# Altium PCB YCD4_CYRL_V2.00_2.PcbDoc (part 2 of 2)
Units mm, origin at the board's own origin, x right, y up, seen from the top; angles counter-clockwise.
Board outline 53 x 53 mm, 6 copper layers (Top Layer, Mid-Layer 1, Mid-Layer 3, Mid-Layer 4, Mid-Layer 5, Bottom Layer), stack 0.996 mm thick; 207 components, 114 nets, 645 pads, 437 vias.
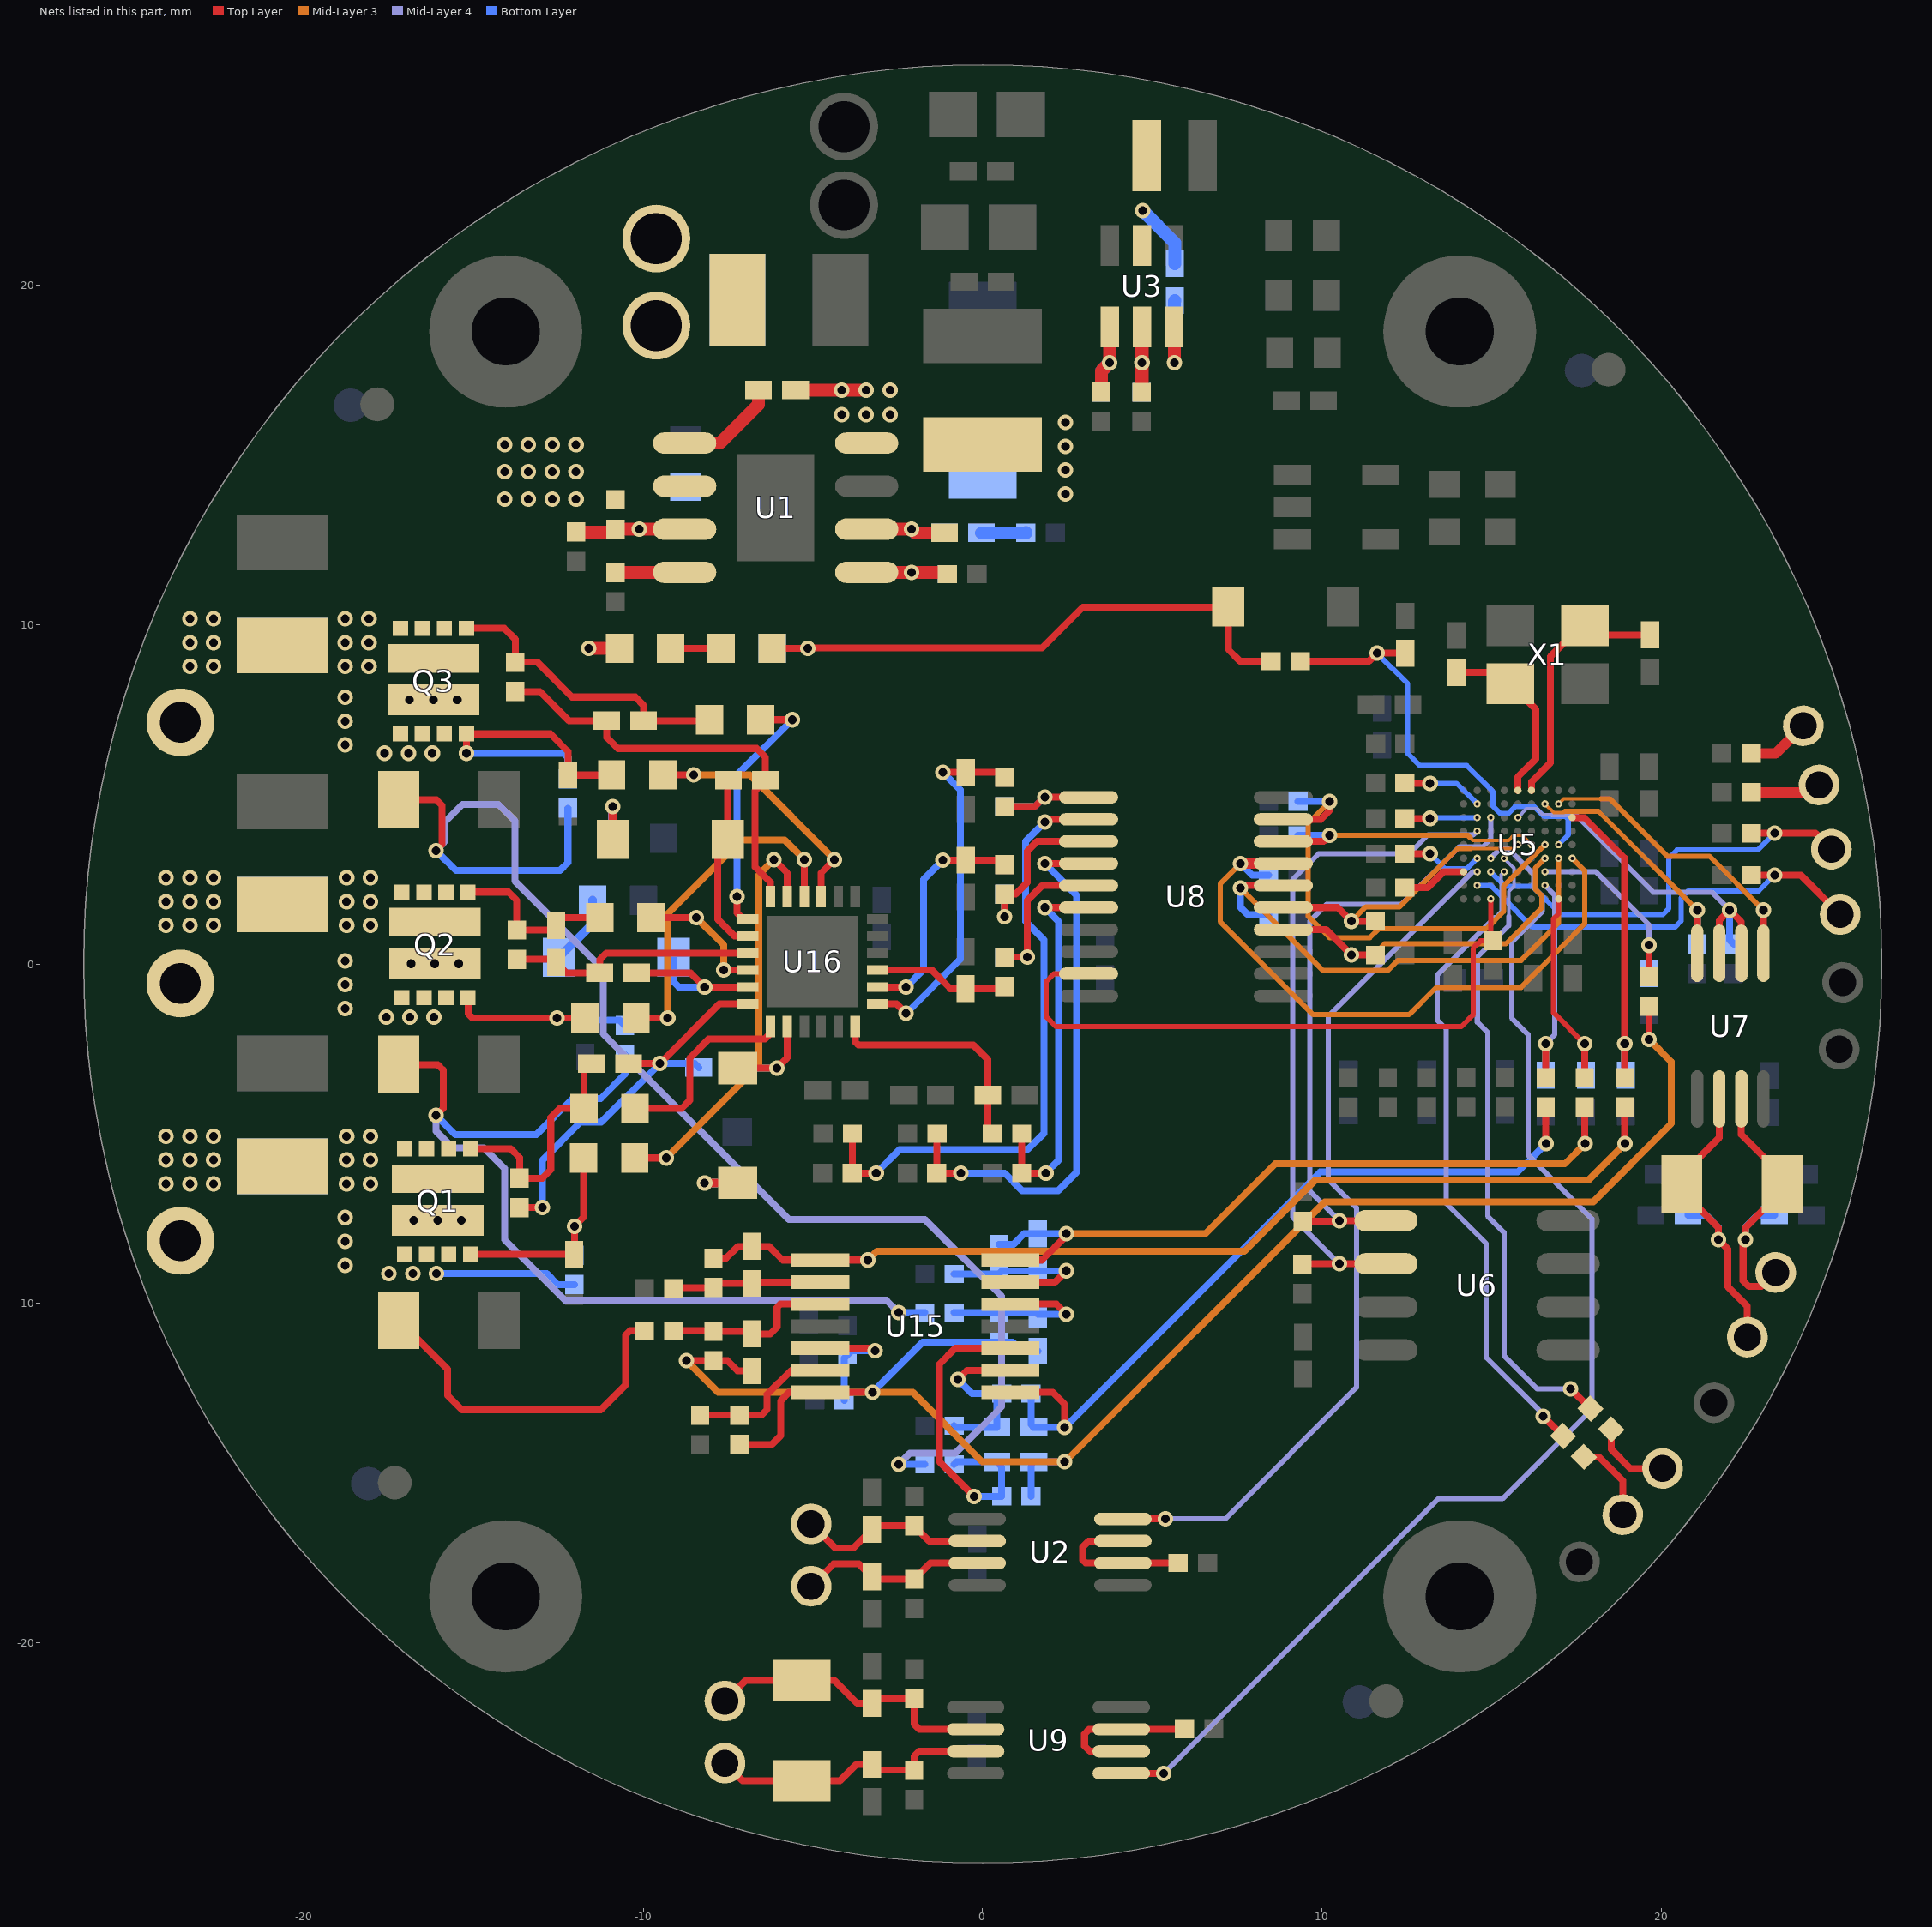
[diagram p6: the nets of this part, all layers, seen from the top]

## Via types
v1: diameter 0.457, hole 0.254, Top Layer to Bottom Layer, tented both sides, 394 vias
v2: diameter 0.203, hole 0.102, Top Layer to Bottom Layer, tented both sides, 43 vias

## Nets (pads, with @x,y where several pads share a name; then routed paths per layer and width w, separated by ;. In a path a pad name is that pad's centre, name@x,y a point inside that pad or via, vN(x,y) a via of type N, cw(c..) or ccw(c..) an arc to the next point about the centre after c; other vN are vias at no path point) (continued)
HIN3: C114.2 R123.2 U16.24 | length 6.8
  Top Layer w0.203: U16.24@-3.76,-1.841 -3.76,-2.296 -3.666,-2.39 -0.275,-2.39 0.151,-2.815 C114.2@0.151,-3.862 0.151,-4.871 R123.2@0.285,-5.005
HO1: R141.1 U16.19 | length 5.8
  Top Layer w0.203: R141.1@-10.245,-4.263 -8.877,-4.263 -8.633,-4.02 -8.633,-2.773 -8.071,-2.211 -6.423,-2.211 -6.26,-2.048 U16.19@-6.26,-1.841
HO2: R130.1 U16.16 | length 3.9
  Top Layer w0.203: R130.1@-9.783,1.366 v1(-8.441,1.366) ; v1(-7.637,-0.179) U16.16@-6.921,-0.179
  Mid-Layer 3 w0.203: v1(-8.441,1.366) -7.637,0.561 v1(-7.637,-0.179)
HO3: R132.1 U16.13 | length 7.7
  Top Layer w0.203: v1(-7.239,1.985) -7.239,1.506 -7.053,1.321 U16.13@-6.921,1.321 ; R132.1@-6.547,7.197 v1(-5.612,7.197)
  Bottom Layer w0.203: v1(-7.239,1.985) -7.239,5.57 v1(-5.612,7.197)
IU_AD: C60.2 R25.1 R64.2 U15.1 | length 29.7
  Top Layer w0.203: R64.2@-7.936,-8.672 -7.563,-8.672 -7.215,-8.325 C60.2@-6.79,-8.325 -6.296,-8.325 -5.894,-8.726 U15.1@-4.783,-8.726 v1(-3.387,-8.726) ; v1@18.925,-5.287 R25.1@18.925,-4.213
  Mid-Layer 3 w0.203: v1(-3.387,-8.726) -3.127,-8.467 7.714,-8.467 9.807,-6.373 17.859,-6.373 v1(18.935,-5.297)
IU_AD_ARM: C29.2 R25.2 U5.J7 | length 9.4
  Top Layer w0.203: U5.J7@17.373,4.315 17.726,4.315 18.925,3.116 v1(18.925,-2.353) R25.2@18.925,-3.348
  Bottom Layer w0.203: v1(18.925,-2.353) 18.925,-3.245 C29.2@18.958,-3.277
IUN: Q1.5 Q1.6 Q1.7 R70.1 R89.1 R90.2 | length 14.8
  Top Layer w0.203: R90.2@-17.215,-10.501 -15.771,-11.945 -15.771,-12.72 -15.349,-13.142 -11.26,-13.142 -10.526,-12.408 -10.526,-10.936 -10.396,-10.806 R70.1@-9.978,-10.806
  Bottom Layer w0.203: v1(-16.098,-9.125) -12.855,-9.125 -12.531,-9.449 R89.1@-12.035,-9.449
  other v1: -17.503,-9.125 -16.801,-9.125
IV_AD: C62.2 R24.1 R66.2 U15.14 | length 21.6
  Top Layer w0.203: U15.14@0.817,-8.726 1.75,-8.726 2.468,-8.009 v1(2.468,-7.953) ; v1@17.742,-5.287 R24.1@17.742,-4.213
  Mid-Layer 3 w0.203: v1(2.468,-7.953) 6.563,-7.953 8.622,-5.894 17.155,-5.894 v1(17.752,-5.297)
  Bottom Layer w0.203: R66.2@0.479,-8.265 0.91,-8.265 1.222,-7.953 C62.2@1.627,-7.953 v1(2.468,-7.953)
IV_AD_ARM: C26.2 R24.2 U5.H1 | length 6.6
  Top Layer w0.152: U5.H1@16.973,1.915 16.973,1.479 16.824,1.33 16.824,-1.436 v1(17.742,-2.353)
  Top Layer w0.203: R24.2@17.742,-3.348 v1(17.742,-2.353)
  Bottom Layer w0.203: v1(17.742,-2.353) 17.742,-3.238 C26.2@17.781,-3.277
IVN: Q2.5 Q2.6 Q2.7 R49.2 R72.1 R100.1 | length 28.2
  Top Layer w0.203: R49.2@-17.215,-2.966 -16.064,-2.966 -15.904,-3.126 -15.904,-4.257 v1(-16.112,-4.465)
  Mid-Layer 4 w0.203: v1(-16.112,-4.465) -16.112,-4.928 -15.624,-5.416 -14.712,-5.416 -14.095,-6.033 -14.095,-8.131 -12.312,-9.914 -2.837,-9.914 v1(-2.476,-10.275)
  Bottom Layer w0.203: v1(-16.112,-4.465) -15.549,-5.028 -13.153,-5.028 -12.088,-3.963 -11.256,-3.963 -10.545,-3.252 R100.1@-10.545,-2.682 ; v1(-2.476,-10.275) R72.1@-1.707,-10.275
  other v1: -17.582,-1.562 -16.879,-1.562 -16.177,-1.562
IW_AD: C61.2 R26.1 R65.2 U15.8 | length 23.1
  Top Layer w0.203: U15.8@0.817,-12.626 2.066,-12.626 2.418,-12.978 v1(2.418,-13.661) ; v1@16.592,-5.287 R26.1@16.592,-4.213
  Bottom Layer w0.203: R65.2@1.425,-12.661 1.425,-13.578 C61.2@1.507,-13.661 v1(2.418,-13.661) 9.945,-6.134 15.765,-6.134 v1(16.602,-5.297)
IW_AD_ARM: C30.2 R26.2 U5.G2 | length 6.8
  Top Layer w0.203: R26.2@16.592,-3.348 v1(16.592,-2.353)
  Mid-Layer 4 w0.152: v2(16.573,2.315) 16.857,2.031 16.857,-2.088 v1(16.592,-2.353)
  Bottom Layer w0.203: C30.2@16.592,-3.277 v1(16.592,-2.353)
IWN: Q3.5 Q3.6 Q3.7 R71.1 R108.1 R111.2 | length 42.1
  Top Layer w0.203: R111.2@-17.215,4.838 -16.105,4.838 -15.931,4.664 -15.931,3.521 v1(-16.112,3.339)
  Mid-Layer 4 w0.203: v1(-16.112,3.339) -15.867,3.584 -15.867,4.171 -15.335,4.704 -14.275,4.704 -13.791,4.22 -13.791,2.44 -11.189,-0.162 -11.189,-2.059 -5.715,-7.533 -1.702,-7.533 0.56,-9.796 0.56,-13.049 -0.81,-14.419 -2.145,-14.419 v1(-2.476,-14.749)
  Bottom Layer w0.203: v1(-16.112,3.339) -15.523,2.751 -13.307,2.751 -12.464,2.751 -12.227,2.989 R108.1@-12.227,4.592 ; v1(-2.476,-14.749) R71.1@-1.707,-14.749
  other v1: -17.626,6.211 -16.924,6.211 -16.222,6.211
LIN1: C111.2 R117.2 U16.1 | length 10.8
  Top Layer w0.203: U16.1@-3.098,-1.179 -2.537,-1.179 v1(-2.258,-1.458) ; v1(-1.174,5.645) C111.2@-0.503,5.645 0.502,5.645 R117.2@0.643,5.505
  Bottom Layer w0.203: v1(-2.258,-1.458) -0.655,0.144 -0.655,5.126 v1(-1.174,5.645)
LIN2: C113.2 R121.2 U16.2 | length 6.9
  Top Layer w0.203: U16.2@-3.098,-0.679 v1(-2.258,-0.679) ; v1(-1.174,3.061) C113.2@-0.503,3.061 0.505,3.061 R121.2@0.643,2.923
  Bottom Layer w0.203: v1(-2.258,-0.679) -1.746,-0.167 -1.746,2.488 v1(-1.174,3.061)
LIN3: C115.2 R144.2 U16.3 | length 4
  Top Layer w0.203: U16.3@-3.098,-0.179 -1.505,-0.179 -0.956,-0.728 C115.2@-0.506,-0.728 0.58,-0.728 R144.2@0.643,-0.665
LO1: R143.1 U16.11 | length 12.3
  Top Layer w0.203: R143.1@-10.255,-5.718 v1(-9.327,-5.718) ; v1(-6.151,3.076) -5.76,2.685 U16.11@-5.76,1.982
  Mid-Layer 3 w0.203: v1(-9.327,-5.718) -6.599,-2.99 -6.599,2.628 v1(-6.151,3.076)
LO2: R145.1 U16.10 | length 10.3
  Top Layer w0.203: R145.1@-10.218,-1.594 v1(-9.283,-1.594) ; U16.10@-5.26,1.982 v1(-5.26,3.076)
  Mid-Layer 3 w0.203: v1(-9.283,-1.594) -9.283,1.478 -7.108,3.654 -5.837,3.654 v1(-5.26,3.076)
LO3: R131.1 U16.9 | length 7.4
  Top Layer w0.203: R131.1@-9.43,5.572 v1(-8.517,5.572) ; U16.9@-4.76,1.982 -4.76,2.685 v1(-4.369,3.076)
  Mid-Layer 3 w0.203: v1(-8.517,5.572) -6.865,5.572 v1(-4.369,3.076)
NetC1_1: C1.1 D1.1 L1.1 U1.8 | length 1.9
  Top Layer w0.381: C1.1@-5.519,16.914 v1@-3.616,16.914
  other v1: 2.438,13.854 2.438,14.556 2.438,15.258 2.438,15.961 -4.157,16.186 -3.442,16.186 -2.727,16.186 -4.157,16.914 -3.442,16.914 -2.727,16.914
NetC1_2: C1.2 U1.1 | length 3.1
  Top Layer w0.381: U1.1@-8.785,15.352 -7.742,15.352 -6.609,16.485 C1.2@-6.609,16.914
NetC8_1: C8.1 C10.1 U1.6 | length 3.2
  Top Layer w0.381: U1.6@-3.42,12.812 v1(-2.097,12.812) -1.991,12.706 C8.1@-1.127,12.706
  Bottom Layer w0.381: v1@-1.991,12.706 C10.1@-1.127,12.706
NetC10_2: C10.2 R2.1 | length 1.3
  Bottom Layer w0.381: C10.2@-0.037,12.706 R2.1@1.275,12.707
NetC11_1: C11.1 U3.6 | length 2.9
  Top Layer w0.381: v1(5.644,17.718) U3.6@5.644,18.771
  Bottom Layer w0.381: v1(5.644,17.718) 5.644,19.53 C11.1@5.662,19.548
NetC11_2: C11.2 L2.1 U3.2 | length 2
  Bottom Layer w0.381: v1(4.714,22.201) 5.662,21.252 C11.2@5.662,20.638
NetC60_1: C60.1 R64.1 R67.2 U15.2 | length 4.4
  Top Layer w0.203: R67.2@-9.112,-9.56 -9.09,-9.538 R64.1@-7.936,-9.538 -7.812,-9.415 C60.1@-6.79,-9.415 -6.751,-9.376 U15.2@-4.783,-9.376
NetC61_1: C61.1 R65.1 R68.2 U15.9 | length 5.5
  Top Layer w0.203: v1(-0.731,-12.246) -0.462,-11.976 U15.9@0.817,-11.976
  Bottom Layer w0.203: R68.2@-0.841,-13.61 -0.79,-13.661 C61.1@0.417,-13.661 0.417,-12.804 R65.1@0.559,-12.661 -0.316,-12.661 v1(-0.731,-12.246)
NetC62_1: C62.1 R66.1 R69.2 U15.13 | length 5.1
  Top Layer w0.203: U15.13@0.817,-9.376 2.134,-9.376 v1(2.468,-9.043)
  Bottom Layer w0.203: R69.2@-0.841,-9.136 0.473,-9.136 R66.1@0.479,-9.13 0.566,-9.043 C62.1@1.627,-9.043 v1(2.468,-9.043)
NetC63_2: C63.2 R70.2 R73.2 U15.3 | length 5.1
  Top Layer w0.203: R70.2@-9.112,-10.806 -7.958,-10.806 R73.2@-7.936,-10.828 -6.864,-10.828 C63.2@-6.79,-10.903 -6.262,-10.903 -6.06,-10.7 -6.06,-10.122 -5.964,-10.026 U15.3@-4.783,-10.026
NetC64_2: C64.2 R71.2 R74.2 U15.10 | length 9.8
  Top Layer w0.203: v1(-0.254,-15.693) -1.278,-14.669 -1.278,-11.798 -0.807,-11.326 U15.10@0.817,-11.326
  Bottom Layer w0.203: R71.2@-0.841,-14.749 -0.769,-14.677 C64.2@0.417,-14.677 0.561,-14.82 R74.2@0.561,-15.693 v1(-0.254,-15.693)
NetC65_2: C65.2 R72.2 R75.2 U15.12 | length 5.1
  Top Layer w0.203: U15.12@0.817,-10.026 2.171,-10.026 v1(2.468,-10.323)
  Bottom Layer w0.203: R72.2@-0.841,-10.275 0.474,-10.275 R75.2@0.479,-10.28 1.585,-10.28 C65.2@1.627,-10.323 v1(2.468,-10.323)
NetC103_2: C103.2 D8.1 U16.20 | length 3.7
  Top Layer w0.203: D8.1@-7.226,-3.072 v1(-6.064,-3.072) -5.76,-2.767 U16.20@-5.76,-1.841
  Bottom Layer w0.203: C103.2@-7.279,-3.054 -7.262,-3.072 v1(-6.064,-3.072)
NetC104_2: C104.2 D9.1 U16.17 | length 5.1
  Top Layer w0.203: C104.2@-10.199,-0.263 -8.612,-0.263 v1(-8.195,-0.679) U16.17@-6.921,-0.679
  Bottom Layer w0.203: D9.1@-9.111,0.191 -9.111,-0.523 -8.955,-0.679 v1(-8.195,-0.679)
NetC105_2: C105.2 D10.1 U16.14 | length 5.3
  Top Layer w0.203: C105.2@-7.492,5.419 -7.517,5.394 D10.1@-7.517,3.675 -7.807,3.385 -7.807,1.31 -7.318,0.821 U16.14@-6.921,0.821
NetCN1_5: pad.5 R15.2 | length 2.1
  Top Layer w0.305: R15.2@22.656,5.057 24.433,5.057 pad.5@24.65,5.274
NetCN1_6: pad.6 R16.2 | length 1.9
  Top Layer w0.305: R16.2@22.651,6.2 23.368,6.2 pad.6@24.186,7.018
NetD8_2: D8.2 R133.1 | length 1.9
  Top Layer w0.254: v1(-8.196,-6.456) D8.2@-7.226,-6.456
  Bottom Layer w0.254: v1(-8.196,-6.456) -8.191,-6.462 R133.1@-7.234,-6.462
NetD9_2: D9.2 R134.1 | length 2.1
  Bottom Layer w0.254: D9.2@-12.496,0.191 -11.503,1.184 R134.1@-11.503,1.878
NetD10_2: D10.2 R135.1 | length 1.9
  Top Layer w0.254: D10.2@-10.902,3.675 v1(-10.902,4.637)
  Bottom Layer w0.254: R135.1@-10.914,3.699 -10.914,4.625 v1(-10.902,4.637)
NetR1_1: R1.1 R124.2 U1.3 | length 3.2
  Top Layer w0.381: R124.2@-11.989,12.729 -10.908,12.729 R1.1@-10.825,12.812 v1(-10.121,12.812) U1.3@-8.785,12.812
NetR3_2: R3.2 U1.4 | length 1.9
  Top Layer w0.381: R3.2@-10.679,11.535 -10.673,11.542 U1.4@-8.785,11.542
NetR4_1: R4.1 R5.1 U1.5 | length 3.5
  Top Layer w0.381: U1.5@-3.42,11.542 v1(-2.097,11.542) -1.093,11.542 R5.1@-1.04,11.489
  Bottom Layer w0.381: v1(-2.097,11.542) -1.093,11.542 R4.1@-1.04,11.489
NetR6_1: R6.1 U5.B4 | length 2.4
  Top Layer w0.203: R6.1@12.444,3.248 v1(13.187,3.248)
  Bottom Layer w0.152: v1(13.187,3.248) 13.624,2.811 14.27,2.811 v2(14.573,3.115)
NetR8_1: R8.1 R9.1 U3.5 | length 2.8
  Top Layer w0.381: R8.1@4.68,16.847 4.694,16.861 v1(4.694,17.718) U3.5@4.694,18.771
  Bottom Layer w0.381: R9.1@4.68,16.847 4.68,17.705 v1(4.694,17.718)
NetR10_1: R10.1 U5.B7 | length 2.1
  Top Layer w0.203: R10.1@12.444,4.29 v1(13.187,4.29)
  Bottom Layer w0.152: v1(13.187,4.29) 13.212,4.315 v2(14.573,4.315)
NetR37_1: R37.1 U2.2 U2.3 | length 4.5
  Top Layer w0.203: U2.3@4.13,-17.007 3.121,-17.007 2.945,-17.183 2.945,-17.563 3.039,-17.657 U2.2@4.13,-17.657 5.759,-17.657 R37.1@5.76,-17.656
NetR40_1: R40.1 R41.1 U3.4 | length 3
  Top Layer w0.381: R41.1@3.502,16.85 3.502,17.476 v1(3.744,17.718) U3.4@3.744,18.771
  Bottom Layer w0.381: R40.1@3.502,16.85 3.502,17.476 v1(3.744,17.718)
NetR43_1: R43.1 U9.2 U9.3 | length 5.4
  Top Layer w0.203: 3.178,-23.208 U9.2@4.085,-23.208 3.158,-23.208 3.001,-23.051 3.001,-22.695 3.138,-22.558 U9.3@4.085,-22.558 5.939,-22.558 R43.1@5.945,-22.553
NetR45_1: R45.1 R50.2 | length 1.5
  Top Layer w0.203: R45.1@-9.199,9.302 R50.2@-7.713,9.302
NetR47_1: R47.1 U5.A3 | length 1.9
  Top Layer w0.203: R47.1@12.444,2.25 13.12,2.25 13.584,2.715 U5.A3@14.173,2.715
NetR53_1: R53.1 U5.B8 | length 2.4
  Top Layer w0.203: R53.1@12.444,5.324 v1(13.187,5.324)
  Bottom Layer w0.152: v1(13.187,5.324) 13.965,5.324 v2(14.573,4.715)
NetR76_1: R76.1 R77.2 U15.6 | length 4.4
  Top Layer w0.203: R77.2@-8.329,-13.301 R77.2@-8.329,-13.301 R76.1@-7.171,-13.3 -6.518,-13.3 -6.354,-13.135 -6.354,-12.692 -5.638,-11.976 U15.6@-4.783,-11.976
NetR78_2: R78.2 R79.2 U15.5 | length 3.9
  Top Layer w0.203: U15.5@-4.783,-11.326 -3.247,-11.326 v1(-3.171,-11.402)
  Bottom Layer w0.203: R79.2@-4.084,-12.861 -4.084,-11.62 R78.2@-3.989,-11.525 -3.866,-11.402 v1(-3.171,-11.402)
OSCIN: C24.1 U5.E9 X1.3 | length 5.4
  Top Layer w0.203: C24.1@13.958,8.588 15.225,8.588 X1.3@15.55,8.262 16.303,7.51 16.303,6.045 15.773,5.515 U5.E9@15.773,5.115
OSCOUT: C27.1 U5.F9 X1.1 | length 7.6
  Top Layer w0.203: U5.F9@16.173,5.115 16.173,5.367 16.732,5.925 16.732,9.06 17.634,9.963 X1.1@17.751,9.963 18.016,9.697 C27.1@19.668,9.697
P+: C5.1 C6.1 C7.2 C69.1 C70.1 C71.1 C106.1 C107.1 C108.1 pad.13@-9.621,18.815 pad.13@-9.621,21.381 Q1.2 Q1.3 Q1.4 Q1.10 Q2.2 Q2.3 Q2.4 Q2.10 Q3.2 Q3.3 Q3.4 Q3.10 R1.2 R45.2 U1.2 | length 0.9
  Top Layer w0.381: v1(-11.609,9.302) R45.2@-10.706,9.302
  other v1: -24.074,-6.48 -23.372,-6.48 -22.67,-6.48 -18.749,-6.48 -18.047,-6.48 -24.074,-5.778 -23.372,-5.778 -22.67,-5.778 -18.749,-5.778 -18.047,-5.778 -24.074,-5.076 -23.372,-5.076 -22.67,-5.076 -18.749,-5.076 -18.047,-5.076 -24.074,1.135 -23.372,1.135 -22.67,1.135 -18.749,1.135 -18.047,1.135 -24.074,1.837 -23.372,1.837 -22.67,1.837 -18.749,1.837 -18.047,1.837 -24.074,2.54 -23.372,2.54 -22.67,2.54 -18.749,2.54 -18.047,2.54 -23.372,8.766 -22.67,8.766 -18.794,8.766 -18.091,8.766 -23.372,9.469 -22.67,9.469 -18.794,9.469 -18.091,9.469 -23.372,10.171 -22.67,10.171 -18.794,10.171 -18.091,10.171 -14.095,13.7 -13.392,13.7 -12.69,13.7 -11.988,13.7 -14.095,14.504 -13.392,14.504 -12.69,14.504 -11.988,14.504 -14.095,15.308 -13.392,15.308 -12.69,15.308 -11.988,15.308
PUH: R115.1 R116.2 U8.12 | length 18.3
  Top Layer w0.203: R115.1@-3.843,-5.005 -3.843,-6.153 R116.2@-3.853,-6.163 v1(-3.14,-6.163) ; v1@1.806,4.185 1.882,4.261 U8.12@3.12,4.261
  Bottom Layer w0.203: v1(-3.14,-6.163) -2.451,-5.474 1.32,-5.474 1.804,-4.99 1.804,0.704 1.26,1.248 1.26,3.614 v1(1.831,4.185)
PUL: R117.1 R118.2 U8.11 | length 3.9
  Top Layer w0.203: R117.1@0.643,4.639 1.533,4.639 1.806,4.911 U8.11@3.12,4.911
  Bottom Layer w0.203: R118.2@0.643,4.639 1.533,4.639 v1@1.806,4.911
  other v1: 1.831,4.911
PVH: R119.1 R120.2 U8.14 | length 16.5
  Top Layer w0.203: R119.1@-1.349,-5.005 -1.349,-6.157 R120.2@-1.355,-6.163 v1(-0.643,-6.163) ; v1@1.806,2.961 v1(1.831,2.961) U8.14@3.12,2.961
  Bottom Layer w0.203: v1(-0.643,-6.163) 0.642,-6.163 1.161,-6.683 2.225,-6.683 2.769,-6.139 2.769,2.024 v1(1.831,2.961)
PVL: R121.1 R122.2 U8.13 | length 5
  Top Layer w0.203: v1(0.643,1.386) R121.1@0.643,2.058 0.971,2.058 1.314,2.4 1.314,3.322 1.604,3.611 U8.13@3.12,3.611
  Bottom Layer w0.203: v1(0.643,1.386) R122.2@0.643,2.058
PWH: R123.1 R140.2 U8.16 | length 11.3
  Top Layer w0.203: R123.1@1.15,-5.005 R140.2@1.15,-6.163 v1(1.863,-6.163) ; v1@1.806,1.661 v1(1.831,1.661) U8.16@3.12,1.661
  Bottom Layer w0.203: v1(1.831,1.661) 2.238,1.254 2.238,-5.788 v1(1.863,-6.163)
PWL: R142.2 R144.1 U8.15 | length 5
  Top Layer w0.203: R144.1@0.643,0.201 v1(1.314,0.201) 1.314,1.87 1.755,2.311 U8.15@3.12,2.311
  Bottom Layer w0.203: R142.2@0.643,0.201 v1(1.314,0.201)
PWM_EN: R7.1 U5.C1 U8.19 | length 19.1
  Top Layer w0.152: U8.19@3.12,-0.289 2.104,-0.289 1.875,-0.518 1.875,-1.563 2.157,-1.846 14.106,-1.846 14.454,-1.498 14.454,0.461 14.676,0.683 14.973,0.683 R7.1@15.037,0.683 14.973,0.747 v2(14.973,1.915)
REF1V65: C63.1 C64.1 C65.1 R27.1 R73.1 R74.1 R75.1 R76.2 U15.7 | length 52.6
  Top Layer w0.203: v1(-8.73,-11.694) R73.1@-7.936,-11.694 -7.524,-11.694 -7.225,-11.993 C63.1@-6.79,-11.993 ; R76.2@-7.171,-14.165 -6.218,-14.165 -5.955,-13.903 -5.955,-12.874 -5.707,-12.626 U15.7@-4.783,-12.626 -3.551,-12.626 ; v1(19.639,-2.226) R27.1@19.639,-1.241
  Mid-Layer 3 w0.203: v1(-8.73,-11.694) -7.797,-12.626 v1(-3.246,-12.626) -2.061,-12.626 -0.01,-14.677 v1(2.418,-14.677) 10.083,-7.012 17.993,-7.012 20.3,-4.705 20.3,-2.887 v1(19.639,-2.226)
  Bottom Layer w0.203: v1(-3.246,-12.626) -1.766,-11.146 R75.1@0.479,-11.146 0.887,-11.146 1.154,-11.413 C65.1@1.627,-11.413 ; R74.1@1.426,-15.693 1.426,-14.758 C64.1@1.507,-14.677 v1(2.418,-14.677)
REF1V65_AD_ARM: C31.1 R27.2 U5.G3 | length 6.1
  Top Layer w0.203: R27.2@19.639,-0.375 v1(19.639,0.551)
  Mid-Layer 4 w0.152: v2(16.573,2.715) 18.078,2.715 19.639,1.153 v1(19.639,0.551)
  Bottom Layer w0.203: v1(19.639,0.551) 19.641,0.549 C31.1@19.641,-0.285
RS232_RX: pad.12@20.039,-14.871 R136.2 | length 2.3
  Top Layer w0.203: R136.2@18.528,-13.719 18.528,-14.309 19.09,-14.871 pad.12@20.039,-14.871
RS232_TX: pad.11 R137.2 | length 2.4
  Top Layer w0.203: R137.2@17.718,-14.528 18.16,-14.528 18.867,-15.234 pad.11@18.867,-16.232
RS485_A: C45.2 pad.10@22.536,-10.998 R34.1 R36.2 U7.6 | length 10.9
  Top Layer w0.203: U7.6@21.711,-3.979 21.711,-5.118 20.604,-6.225 R34.1@20.604,-6.482 20.604,-6.693 21.687,-7.776 v1(21.687,-8.126) 21.965,-8.403 21.965,-9.515 22.536,-10.086 pad.10@22.536,-10.998
  Bottom Layer w0.203: R36.2@20.662,-6.211 20.788,-6.337 C45.2@20.788,-7.406 21.328,-7.406 21.687,-7.765 v1(21.687,-8.126)
RS485_B: C44.1 pad.9@23.372,-9.09 R33.1 R34.2 U7.7 | length 10.2
  Top Layer w0.203: U7.7@22.361,-3.979 22.361,-5.034 23.562,-6.234 R34.2@23.562,-6.482 23.562,-6.693 22.479,-7.776 v1(22.479,-8.126) 22.413,-8.192 22.413,-9.341 22.58,-9.508 22.954,-9.508 pad.9@23.372,-9.09
  Bottom Layer w0.203: v1(22.479,-8.126) 22.479,-7.759 22.832,-7.406 C44.1@23.337,-7.406 23.337,-6.339 R33.1@23.465,-6.211
RS485_RE: R32.1 U5.E7 U7.2 U7.3 | length 11.5
  Top Layer w0.203: U7.3@21.711,0.313 21.711,1.281 v1(22.016,1.586) 22.361,1.241 U7.2@22.361,0.313
  Mid-Layer 4 w0.102: v2(15.773,4.315) 16.028,4.569 16.337,4.569 16.51,4.396 16.793,4.396
  Mid-Layer 4 w0.152: 16.793,4.396 17.484,4.396 19.766,2.114 21.489,2.114 v1(22.016,1.586)
  Bottom Layer w0.203: v1(22.016,1.586) 22.016,0.704 R32.1@22.137,0.583
RS485_RX: U5.H8 U7.1 | length 8.7
  Top Layer w0.203: U7.1@23.012,0.313 v1(23.012,1.586)
  Mid-Layer 3 w0.102: v2(16.973,4.715) 17.119,4.861 18.229,4.861
  Mid-Layer 3 w0.152: 18.229,4.861 18.491,4.861 20.175,3.176 21.422,3.176 v1(23.012,1.586)
RS485_TX: R35.2 U5.G8 U7.4 | length 8.1
  Top Layer w0.203: U7.4@21.061,0.313 v1(21.061,1.586)
  Mid-Layer 3 w0.102: v2(16.573,4.715) 16.833,4.456 17.121,4.456 17.165,4.5
  Mid-Layer 3 w0.152: 17.165,4.5 18.148,4.5 v1(21.061,1.586)
  Bottom Layer w0.203: R35.2@21.045,0.583 21.061,0.6 v1(21.061,1.586)
SCL: R13.1 U5.B6 U6.6 | length 20.4
  Top Layer w0.203: R13.1@9.423,-8.848 9.434,-8.837 v1(10.512,-8.837) U6.6@11.888,-8.837
  Mid-Layer 4 w0.152: v1(10.512,-8.837) 9.135,-7.46 9.135,2.482 9.895,3.242 12.565,3.242 13.127,3.804 14.463,3.804 v2(14.573,3.915)
SDA: R14.2 U5.C7 U6.5 | length 18.6
  Top Layer w0.203: R14.2@9.43,-7.585 10.494,-7.585 v1(10.512,-7.567) U6.5@11.888,-7.567
  Mid-Layer 4 w0.152: v1(10.512,-7.567) 9.648,-6.704 9.648,1.27 10.137,1.758 12.353,1.758 14.044,3.449 14.736,3.449 14.973,3.687 v2(14.973,4.315)
SPI_CLK: U2.4 U5.B3 | length 25.9
  Top Layer w0.203: U2.4@4.13,-16.357 v1(5.382,-16.357)
  Mid-Layer 4 w0.152: v1(5.382,-16.357) 7.143,-16.357 11.016,-12.484 11.016,-7.188 10.182,-6.354 10.182,-1.545 12.898,1.171 14.443,2.715 v2(14.573,2.715)
SPI_CLK+: C48.2 pad.12@-5.057,-16.503 R38.2 U2.6 | length 5.6
  Top Layer w0.203: pad.12@-5.057,-16.503 -4.345,-17.215 -3.811,-17.215 C48.2@-3.263,-16.668 -3.156,-16.561 R38.2@-2.022,-16.561 -1.576,-17.007 U2.6@-0.162,-17.007
SPI_CLK-: C47.1 pad.12@-5.057,-18.341 R17.1 U2.7 | length 5.6
  Top Layer w0.203: pad.12@-5.057,-18.341 -4.393,-17.677 -3.65,-17.677 C47.1@-3.263,-18.065 -3.192,-18.136 R17.1@-2.022,-18.136 -1.544,-17.657 U2.7@-0.162,-17.657
SPI_DATA: U5.C4 U9.1 | length 37.2
  Top Layer w0.203: U9.1@4.085,-23.859 v1(5.337,-23.859)
  Mid-Layer 4 w0.152: v1(5.337,-23.859) 13.431,-15.764 15.321,-15.764 17.954,-13.131 17.954,-7.511 16.073,-5.629 16.073,-2.076 15.591,-1.594 15.591,0.489 15.591,0.642 16.486,1.537 16.486,2 16.237,2.249 16.237,2.648 15.481,3.404 15.263,3.404 v2(14.973,3.115)
SPI_DATA+: C51.2 pad.10@-7.597,-21.724 R42.1 R44.2 U9.6 | length 8.8
  Top Layer w0.203: pad.10@-7.597,-21.724 -6.991,-21.118 R42.1@-5.337,-21.118 -4.377,-21.118 -3.702,-21.793 C51.2@-3.263,-21.793 -3.128,-21.658 R44.2@-2.022,-21.658 -2.022,-22.405 -1.869,-22.558 U9.6@-0.207,-22.558
SPI_DATA-: C50.1 pad.10@-7.597,-23.56 R39.1 R42.2 U9.7 | length 8.3
  Top Layer w0.203: pad.10@-7.597,-23.56 -7.081,-24.076 R42.2@-5.337,-24.076 -4.208,-24.076 -3.729,-23.597 C50.1@-3.263,-23.597 -3.099,-23.761 R39.1@-2.022,-23.761 -2.022,-23.35 -1.88,-23.208 U9.7@-0.207,-23.208
SWCLK: pad.3 R12.2 U5.C3 | length 13.3
  Top Layer w0.203: R12.2@22.656,3.851 v1(23.339,3.851) 24.543,3.851 pad.3@25.013,3.381
  Bottom Layer w0.152: v2(14.973,2.715) 15.407,2.282 16.209,2.282 17.036,1.454 18.804,1.454 20.048,1.454 20.226,1.632 20.226,3.118 20.464,3.356 22.844,3.356 v1(23.339,3.851)
SWDIO: pad.2 R11.2 U5.B2 | length 13.4
  Top Layer w0.203: R11.2@22.656,2.618 v1(23.339,2.618) 24.11,2.618 pad.2@25.271,1.457
  Bottom Layer w0.152: v2(14.573,2.315) 14.97,2.315 15.35,1.935 16.2,1.085 18.804,1.085 20.403,1.085 20.583,1.265 20.583,1.942 20.79,2.149 22.871,2.149 v1(23.339,2.618)
U: C103.1 C116.1 pad.9@-23.648,-8.157 Q1.9 R88.1 U16.18 | length 12.2
  Top Layer w0.203: R88.1@-13.653,-7.18 v1(-12.983,-7.18) ; C116.1@-10.44,-2.937 v1(-9.517,-2.937) -7.759,-1.179 U16.18@-6.921,-1.179
  Bottom Layer w0.203: v1(-12.983,-7.18) -12.983,-5.789 -11.859,-4.666 -11.246,-4.666 v1(-9.517,-2.937) -8.487,-2.937 C103.1@-8.37,-3.054
  other v1: -18.794,-8.881 -18.794,-8.178 -16.769,-7.556 -16.067,-7.556 -15.364,-7.556 -18.794,-7.476
UART_RX: R137.1 U5.D3 | length 19
  Top Layer w0.203: v1(16.521,-13.33) R137.1@17.106,-13.916
  Mid-Layer 4 w0.102: 15.096,1.37 15.282,1.556 15.282,2.623 v2(15.373,2.715)
  Mid-Layer 4 w0.152: 15.096,1.37 13.393,-0.332 13.393,-1.648 13.665,-1.921 13.665,-7.065 14.836,-8.235 14.836,-11.596 v1@16.545,-13.306
UART_TX: R136.1 U5.D4 | length 18.8
  Top Layer w0.203: v1(17.33,-12.521) R136.1@17.916,-13.106
  Mid-Layer 4 w0.102: v2(15.373,3.115) 15.664,2.824 15.664,2.292 15.507,2.135 15.507,1.403
  Mid-Layer 4 w0.152: 15.507,1.403 15.507,1.13 14.577,0.201 14.577,-1.713 14.882,-2.018 14.882,-7.435 15.363,-7.916 15.363,-11.545 16.338,-12.521 v1(17.33,-12.521)
UDC_AD: D11.2 R28.1 R50.1 R54.2 | length 17.6
  Top Layer w0.203: R50.1@-6.206,9.302 v1(-5.159,9.302) -5.15,9.312 1.75,9.312 2.958,10.519 D11.2@7.236,10.519 7.236,9.272 7.587,8.921 R28.1@8.499,8.921
  Bottom Layer w0.203: R54.2@-6.206,9.302 v1(-5.159,9.302)
UDC_AD_ARM: C32.1 R28.2 U5.H5 | length 13.3
  Top Layer w0.203: R28.2@9.364,8.921 11.385,8.921 v1(11.624,9.159) C32.1@12.45,9.159
  Bottom Layer w0.152: v1(11.624,9.159) 12.529,8.254 12.529,6.205 12.885,5.849 12.898,5.849 14.268,5.849 15.042,5.074 15.042,4.645 15.255,4.433 15.486,4.433 15.689,4.635 16.258,4.635 16.551,4.342 17.18,4.342 17.257,4.264 17.257,3.799 v2(16.973,3.515)
UH: C116.2 Q1.1 R88.2 R141.2 | length 7.2
  Top Layer w0.203: Q1.1@-15.091,-5.446 -13.915,-5.446 -13.653,-5.707 R88.2@-13.653,-6.314 -12.979,-6.314 -12.732,-6.067 ; -12.732,-6.042 -12.732,-4.522 -12.473,-4.263 R141.2@-11.752,-4.263 -11.752,-3.159 C116.2@-11.53,-2.937
UH_ARM: R22.1 U5.F5 U8.8 | length 8.6
  Top Layer w0.203: U8.8@8.862,3.611 10.051,3.611 v1(10.229,3.789)
  Mid-Layer 3 w0.102: 14.365,3.725 14.446,3.644 15.5,3.644 15.649,3.793 15.896,3.793 v2(16.173,3.515)
  Mid-Layer 3 w0.152: v1(10.229,3.789) 14.301,3.789 14.365,3.725
  Bottom Layer w0.203: R22.1@9.294,3.789 v1(10.229,3.789)
UL: C117.2 Q1.8 R89.2 R143.2 | length 6.9
  Top Layer w0.203: Q1.8@-15.091,-8.556 -12.05,-8.556 -12.045,-8.55 C117.2@-12.045,-8.562 -12.035,-8.552 v1(-12.035,-7.737) -11.762,-7.464 R143.2@-11.762,-5.718
  Bottom Layer w0.203: R89.2@-12.035,-8.584 v1(-12.035,-7.737)
UL_ARM: R21.1 U5.G5 U8.9 | length 15.1
  Top Layer w0.203: U8.9@8.862,4.261 9.966,4.261 10.229,4.525 v1(10.229,4.784)
  Mid-Layer 3 w0.152: v1(10.229,4.784) 9.598,4.153 9.598,1.401 10.224,0.775 11.411,0.775 11.669,1.032 12.898,1.032 14.841,1.032 15.35,1.541 15.35,2.291 15.795,2.736 v2(16.573,3.515)
  Bottom Layer w0.203: R21.1@9.294,4.784 v1(10.229,4.784)
V: C100.1 C104.1 pad.9@-23.648,-0.579 Q2.9 R97.1 U16.15 | length 7.4
  Top Layer w0.203: R97.1@-13.732,0.134 -12.664,0.134 C100.1@-12.573,0.043 -12.267,-0.263 C104.1@-11.29,-0.263 -11.29,0.124 -11.093,0.321 U16.15@-6.921,0.321
  other v1: -18.794,-1.314 -18.794,-0.611 -16.848,0.007 -16.145,0.007 -15.443,0.007 -18.794,0.091
VH: C100.2 Q2.1 R97.2 R130.2 | length 5
  Top Layer w0.203: Q2.1@-15.17,2.117 -13.975,2.117 -13.732,1.874 -13.732,0.999 -12.707,0.999 C100.2@-12.573,1.133 -12.341,1.366 R130.2@-11.29,1.366
VH_ARM: R19.1 U5.H4 U8.6 | length 15.6
  Top Layer w0.203: v1(7.599,2.235) 7.675,2.312 U8.6@8.862,2.312
  Mid-Layer 3 w0.152: v1(7.599,2.235) 10.027,-0.193 11.941,-0.193 12.237,0.102 15.871,0.102 16.257,0.489 16.973,1.204 v2(16.973,3.115)
  Bottom Layer w0.203: v1(7.599,2.235) 7.599,1.671 7.813,1.457 R19.1@8.429,1.457
VL: C99.2 Q2.8 R100.2 R145.2 | length 6.1
  Top Layer w0.203: Q2.8@-15.17,-0.993 -15.17,-1.465 -15.041,-1.594 v1(-12.55,-1.594) R145.2@-11.724,-1.594
  Bottom Layer w0.203: v1(-12.55,-1.594) -11.776,-1.594 C99.2@-11.716,-1.653 -10.708,-1.653 R100.2@-10.545,-1.816
VL_ARM: R23.1 U5.J4 U8.7 | length 19.3
  Top Layer w0.305: v1(7.599,2.961) U8.7@8.862,2.961
  Mid-Layer 3 w0.152: v1(7.599,2.961) 6.997,2.36 6.997,1.249 9.741,-1.496 12.565,-1.496 13.371,-0.69 15.87,-0.69 17.048,0.489 17.738,1.178 17.738,2.75 v2(17.373,3.115)
  Bottom Layer w0.203: v1(7.599,2.961) 7.942,2.618 R23.1@8.427,2.618
W: C102.1 C105.1 pad.9@-23.648,7.116 Q3.9 R101.1 U16.12 | length 12.9
  Top Layer w0.203: R101.1@-13.777,8.029 -13.055,8.029 -12.195,7.169 C102.1@-11.087,7.169 -11.087,6.678 -10.759,6.351 -6.663,6.351 -6.402,6.09 C105.1@-6.402,5.419 -6.711,5.11 -6.711,2.86 -6.26,2.409 U16.12@-6.26,1.982
  other v1: -18.794,6.454 -18.794,7.156 -16.892,7.78 -16.19,7.78 -15.488,7.78 -18.794,7.859
WH: C102.2 Q3.1 R101.2 R132.2 | length 9
  Top Layer w0.203: Q3.1@-15.215,9.89 -14.101,9.89 -13.777,9.566 R101.2@-13.777,8.895 -13.132,8.895 -12.104,7.867 -10.24,7.867 -9.996,7.623 C102.2@-9.996,7.169 -8.081,7.169 R132.2@-8.053,7.197
WH_ARM: R18.1 U5.G4 U8.4 | length 10.9
  Top Layer w0.203: U8.4@8.862,1.011 10.124,1.011 v1(10.869,0.267) ; v1@10.818,0.267 10.824,0.261 R18.1@11.577,0.261
  Mid-Layer 3 w0.152: v1(10.869,0.267) 11.516,0.267 11.842,0.593 12.898,0.593 15.42,0.593 16.476,1.65 16.476,2.017 16.287,2.206 16.287,2.828 v2(16.573,3.115)
WL: C101.2 Q3.8 R108.2 R131.2 | length 9.4
  Top Layer w0.203: v1(-15.215,6.211) Q3.8@-15.215,6.78 -12.743,6.78 -12.225,6.262 C101.2@-12.225,5.572 -12.219,5.566 -10.943,5.566 R131.2@-10.937,5.572
  Bottom Layer w0.203: v1(-15.215,6.211) -12.364,6.211 -12.227,6.074 R108.2@-12.227,5.458
WL_ARM: R20.1 U5.E5 U8.5 | length 8.8
  Top Layer w0.203: U8.5@8.862,1.662 10.466,1.662 v1(10.869,1.258) ; v1@10.823,1.253 R20.1@11.577,1.253
  Mid-Layer 3 w0.102: 14.382,3.399 15.657,3.399 v2(15.773,3.515)
  Mid-Layer 3 w0.152: v1(10.869,1.258) 11.297,1.686 12.287,1.686 12.898,2.298 13.999,3.399 14.382,3.399
pads on no net: U2.1 U4.4 U5.A2 U5.A5 U5.A6 U5.A7 U5.B5 U5.C2 U5.C5 U5.C6 U5.C8 U5.D1 U5.D2 U5.D5 U5.D7 U5.E2 U5.E3 U5.E4 U5.E6 U5.E8 U5.F2 U5.F3 U5.F4 U5.F8 U5.G1 U5.G7 U5.G9 U5.H2 U5.H3 U5.H7 U5.J3 U5.J8 U8.17 U8.18 U9.4 U16.5 U16.7 U16.8 U16.21

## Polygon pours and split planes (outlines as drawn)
GND on Top Layer "NONET_L03_P-001" (solid, remove dead copper, pour order 189): 13.574,11.477 20.668,11.477 20.866,11.278 20.866,6.805 20.75,6.689 17.845,6.689 17.137,5.981 14.337,5.981 13.161,7.157 13.161,11.064
IWN on Top Layer "NONET_L03_P-001" (solid, remove dead copper, pour order 148): -17.883,3.794 -17.884,6.92 -17.728,7.076 -15.711,7.076 -15.672,7.037 -15.672,6.004 -15.753,5.923 -16.291,5.923 -16.361,5.852 -16.361,3.802 -16.477,3.686 -17.775,3.686
GND on Top Layer "NONET_L03_P-001" (solid, remove dead copper, pour order 188): 13.054,13.291 12.899,13.136 12.899,11.938 13.025,11.778 19.395,11.774 19.652,12.031 19.652,13.068 19.43,13.291
3.3V on Top Layer "NONET_L03_P-001" (solid, remove dead copper, pour order 187): 11.109,13.679 19.395,13.673 19.652,13.931 19.652,15.447 19.442,15.657 11.216,15.657 10.953,15.394 10.953,13.835
GND on Top Layer "NONET_L03_P-001" (solid, remove dead copper, pour order 185): 11.41,23.678 11.584,23.504 11.584,20.958 11.355,20.729 11.355,16.271 11.209,16.124 9.662,16.122 9.607,16.177 9.607,23.537 9.748,23.678
5V on Top Layer "NONET_L03_P-001" (solid, remove dead copper, pour order 183): 7.371,12.279 7.484,12.167 9.688,12.167 9.762,12.241 9.762,12.846 9.712,12.896 8.352,12.896 8.277,12.971 8.277,14.028 8.34,14.093 9.678,14.093 9.736,14.151 9.736,15.478 9.256,15.958 9.256,24.487 7.201,25.198 6.218,25.198 6,24.981 5.998,22.489 6.096,22.392 7.129,22.392 7.371,22.149
NetC11_2 on Top Layer "NONET_L03_P-001" (solid, remove dead copper, pour order 182): 4.375,20.177 5.07,20.18 5.14,20.25 5.14,22.039 5.38,22.279 5.38,25.543 5.198,25.726 3.558,25.726 3.4,25.567 3.4,22.346 3.525,22.221 4.154,22.221 4.297,22.079 4.297,20.256
GND on Top Layer "NONET_L03_P-001" (solid, remove dead copper, pour order 181): 5.353,20.372 5.352,21.882 5.429,21.96 6.797,21.96 6.972,21.785 6.971,20.289 6.902,20.219 5.506,20.219
10.4V on Top Layer "NONET_L03_P-001" (solid, remove dead copper, pour order 179): -1.904,17.621 -1.848,17.566 2.535,17.562 2.837,17.864 2.837,19.94 2.958,20.06 3.933,20.06 4.055,20.183 4.055,21.86 3.959,21.957 3.264,21.957 3.114,22.106 3.114,25.64 2.717,26.038 0.431,26.038 0.24,25.846 0.24,19.627 0.009,19.396 -1.787,19.396 -1.904,19.279
NetC1_1 on Top Layer "NONET_L03_P-001" (solid, remove dead copper, pour order 177): -4.352,15.156 -4.352,17.102 -4.125,17.329 -2.787,17.329 -1.742,16.284 2.547,16.284 2.764,16.067 2.764,13.551 2.571,13.358 -1.982,13.358 -2.1,13.476 -2.1,14.395 -2.621,14.916 -4.122,14.916
P+ on Top Layer "NONET_L03_P-001" (solid, remove dead copper, pour order 175): -14.791,15.3 -14.499,15.593 -12.779,15.593 -10.301,15.593 -10.162,15.454 -10.162,14.862 -9.958,14.684 -7.901,14.684 -7.828,14.611 -7.828,13.591 -7.95,13.469 -14.536,13.469 -14.791,13.724
GND on Top Layer "NONET_L03_P-001" (solid, remove dead copper, pour order 170): -14.87,-11.459 -14.867,-9.556 -14.795,-9.484 -13.127,-9.484 -12.874,-9.736 -12.874,-11.476 -13.054,-11.655 -14.674,-11.655
GND on Top Layer "NONET_L03_P-001" (solid, remove dead copper, pour order 169): -14.87,-3.924 -14.867,-2.021 -14.795,-1.948 -13.03,-1.948 -12.874,-2.104 -12.874,-3.941 -13.054,-4.12 -14.674,-4.12
GND on Top Layer "NONET_L03_P-001" (solid, remove dead copper, pour order 168): -14.87,3.881 -14.867,5.784 -14.795,5.856 -13.127,5.856 -12.874,5.604 -12.874,3.864 -13.054,3.684 -14.674,3.684
W on Top Layer "Top Layer-U" (solid, remove dead copper, pour order 167): -24.811,7.992 -24.803,6.297 -24.613,6.106 -18.434,6.106 -18.229,6.311 -18.229,7.205 -18.109,7.325 -14.84,7.325 -13.631,7.322 -13.516,7.437 -13.516,8.26 -13.592,8.336 -14.739,8.336 -14.84,8.235 -24.568,8.235
U on Top Layer "NONET_L03_P-001" (solid, remove dead copper, pour order 158): -14.473,-7.101 -14.273,-6.901 -13.55,-6.901 -13.4,-7.051 -13.4,-7.868 -13.543,-8.011 -14.717,-8.011 -17.986,-8.011 -18.105,-8.131 -18.105,-9.06 -18.275,-9.23 -24.103,-9.23 -24.682,-8.651 -24.688,-7.344 -24.445,-7.101
P+ on Top Layer "NONET_L03_P-001" (solid, remove dead copper, pour order 157): -24.498,-6.76 -14.753,-6.76 -14.715,-6.722 -14.715,-5.92 -15.471,-5.92 -15.512,-5.88 -15.512,-4.895 -15.608,-4.799 -24.536,-4.799 -24.734,-4.996 -24.734,-6.524
IUN on Top Layer "NONET_L03_P-001" (solid, remove dead copper, pour order 156): -17.885,-11.537 -17.886,-8.455 -17.691,-8.26 -15.588,-8.26 -15.548,-8.299 -15.548,-9.297 -15.639,-9.388 -16.122,-9.388 -16.238,-9.504 -16.238,-11.534 -16.353,-11.65 -17.772,-11.65
IVN on Top Layer "NONET_L03_P-001" (solid, remove dead copper, pour order 155): -17.838,-3.98 -17.839,-0.853 -17.683,-0.697 -15.667,-0.697 -15.627,-0.736 -15.627,-1.769 -15.701,-1.842 -16.214,-1.842 -16.316,-1.944 -16.316,-3.972 -16.432,-4.088 -17.73,-4.088
GND on Top Layer "NONET_L03_P-001" (solid, remove dead copper, pour order 154): -24.816,-2.286 -24.596,-2.066 -18.558,-2.066 -18.378,-2.246 -18.378,-3.846 -18.596,-4.065 -24.623,-4.065 -24.806,-3.883
V on Top Layer "NONET_L03_P-001" (solid, remove dead copper, pour order 153): -14.795,0.462 -13.487,0.462 -13.457,0.431 -13.457,-0.371 -13.534,-0.448 -18.064,-0.448 -18.184,-0.568 -18.184,-1.462 -18.389,-1.667 -24.568,-1.667 -24.759,-1.476 -24.766,0.219 -24.524,0.462
P+ on Top Layer "NONET_L03_P-001" (solid, remove dead copper, pour order 152): -24.576,0.803 -14.832,0.803 -14.794,0.841 -14.794,1.643 -15.55,1.643 -15.59,1.683 -15.59,2.668 -15.687,2.764 -24.615,2.764 -24.812,2.567 -24.812,1.039
GND on Top Layer "NONET_L03_P-001" (solid, remove dead copper, pour order 151): -21.981,11.502 -21.981,13.984 -21.785,14.179 -17.106,14.179 -16.986,14.059 -16.986,11.56 -17.104,11.442 -21.921,11.442
P+ on Top Layer "NONET_L03_P-001" (solid, remove dead copper, pour order 150): -24.123,8.576 -14.876,8.576 -14.838,8.614 -14.838,9.416 -15.595,9.416 -15.635,9.456 -15.635,10.188 -15.778,10.331 -23.713,10.331 -24.24,9.804 -24.24,8.694
GND on Top Layer "NONET_L03_P-001" (solid, remove dead copper, pour order 149): -24.815,5.354 -24.55,5.619 -18.573,5.619 -18.378,5.423 -18.378,3.972 -18.596,3.753 -24.623,3.753 -24.806,3.936
GND on Top Layer "NONET_L03_P-001" (solid, remove dead copper, pour order 146): -0.295,25.771 -0.135,25.611 -0.135,22.715 -0.29,22.56 -0.29,20.037 -0.494,19.833 -2.275,19.833 -2.46,19.674 -2.46,18.306 -3.013,17.753 -5.234,17.748 -5.412,17.926 -5.412,25.475 -5.115,25.771
P+ on Top Layer "tgr" (solid, remove dead copper, pour order 0): -10.929,22.06 -10.573,22.417 -6.862,22.417 -6.512,22.067 -6.512,18.058 -6.872,17.698 -10.685,17.698 -10.929,17.942
GND on Bottom Layer "NONET_L03_P-001" (solid, remove dead copper, pour order 205): -14.87,-11.459 -14.867,-9.556 -14.795,-9.484 -13.127,-9.484 -12.874,-9.736 -12.874,-11.476 -13.054,-11.655 -14.674,-11.655
GND on Bottom Layer "NONET_L03_P-001" (solid, remove dead copper, pour order 204): -14.87,-3.924 -14.867,-2.021 -14.795,-1.948 -13.03,-1.948 -12.874,-2.104 -12.874,-3.941 -13.054,-4.12 -14.674,-4.12
GND on Bottom Layer "NONET_L03_P-001" (solid, remove dead copper, pour order 203): -14.87,3.881 -14.867,5.784 -14.795,5.856 -13.127,5.856 -12.874,5.604 -12.874,3.864 -13.054,3.684 -14.674,3.684
IUN on Bottom Layer "NONET_L03_P-001" (solid, remove dead copper, pour order 202): -17.885,-11.537 -17.886,-8.455 -17.691,-8.26 -15.588,-8.26 -15.548,-8.299 -15.548,-9.297 -15.639,-9.388 -16.122,-9.388 -16.238,-9.504 -16.238,-11.534 -16.353,-11.65 -17.772,-11.65
IVN on Bottom Layer "NONET_L03_P-001" (solid, remove dead copper, pour order 201): -17.838,-3.98 -17.839,-0.853 -17.683,-0.697 -15.667,-0.697 -15.627,-0.736 -15.627,-1.769 -15.701,-1.842 -16.214,-1.842 -16.316,-1.944 -16.316,-3.972 -16.432,-4.088 -17.73,-4.088
IWN on Bottom Layer "NONET_L03_P-001" (solid, remove dead copper, pour order 200): -17.883,3.794 -17.884,6.92 -17.728,7.076 -15.711,7.076 -15.672,7.037 -15.672,6.004 -15.753,5.923 -16.291,5.923 -16.361,5.852 -16.361,3.802 -16.477,3.686 -17.775,3.686
GND on Bottom Layer "NONET_L03_P-001" (solid, remove dead copper, pour order 197): -7.241,15.018 -4.968,15.018 -4.961,11.872 -7.258,11.865
GND on Bottom Layer "NONET_L03_P-001" (solid, remove dead copper, pour order 186): 11.41,23.678 11.584,23.504 11.584,20.958 11.355,20.729 11.355,16.271 11.209,16.124 9.662,16.122 9.607,16.177 9.607,23.537 9.748,23.678
5V on Bottom Layer "NONET_L03_P-001" (solid, remove dead copper, pour order 184): 7.38,21.443 7.521,21.584 8.943,21.584 9.159,21.367 9.159,14.534 8.921,14.296 7.481,14.296 7.367,14.41
10.4V on Bottom Layer "NONET_L03_P-001" (solid, remove dead copper, pour order 180): 0.193,20.678 0.193,23.401 0.417,23.625 0.417,25.765 0.672,26.02 2.741,26.02 3.087,25.673 3.087,20.894 2.771,20.578 0.293,20.578
NetC1_1 on Bottom Layer "NONET_L03_P-001" (solid, remove dead copper, pour order 178): -4.352,15.156 -4.352,17.102 -4.125,17.329 -2.787,17.329 -1.742,16.284 2.547,16.284 2.764,16.067 2.764,13.551 2.571,13.358 -1.982,13.358 -2.1,13.476 -2.1,14.395 -2.621,14.916 -4.122,14.916
P+ on Bottom Layer "NONET_L03_P-001" (solid, remove dead copper, pour order 176): -14.791,15.3 -14.499,15.593 -12.779,15.593 -10.301,15.593 -10.162,15.454 -10.162,14.862 -9.958,14.684 -7.901,14.684 -7.828,14.611 -7.828,13.591 -7.95,13.469 -14.536,13.469 -14.791,13.724
GND on Bottom Layer "NONET_L03_P-001" (solid, remove dead copper, pour order 173): -0.295,25.771 -0.135,25.611 -0.135,22.715 -0.29,22.56 -0.29,20.235 -0.163,20.108 0.942,20.108 1.165,19.885 1.165,18.203 1.042,18.08 -2.686,18.08 -3.013,17.753 -5.234,17.748 -5.412,17.926 -5.412,25.475 -5.115,25.771
P+ on Bottom Layer "tgr" (solid, remove dead copper, pour order 172): -10.929,22.06 -10.573,22.417 -6.862,22.417 -6.512,22.067 -6.512,18.058 -6.872,17.698 -10.685,17.698 -10.929,17.942
P+ on Bottom Layer "NONET_L03_P-001" (solid, remove dead copper, pour order 165): -24.123,8.576 -14.876,8.576 -14.838,8.614 -14.838,9.416 -15.595,9.416 -15.635,9.456 -15.635,10.188 -15.778,10.331 -23.713,10.331 -24.24,9.804 -24.24,8.694
P+ on Bottom Layer "NONET_L03_P-001" (solid, remove dead copper, pour order 164): -24.498,-6.76 -14.753,-6.76 -14.715,-6.722 -14.715,-5.92 -15.471,-5.92 -15.512,-5.88 -15.512,-5.676 -16.389,-4.799 -24.536,-4.799 -24.734,-4.996 -24.734,-6.524
GND on Bottom Layer "NONET_L03_P-001" (solid, remove dead copper, pour order 163): -24.816,-2.286 -24.596,-2.066 -18.558,-2.066 -18.378,-2.246 -18.378,-3.846 -18.596,-4.065 -24.623,-4.065 -24.806,-3.883
P+ on Bottom Layer "NONET_L03_P-001" (solid, remove dead copper, pour order 162): -24.576,0.803 -14.832,0.803 -14.794,0.841 -14.794,1.643 -15.55,1.643 -15.59,1.683 -15.59,2.34 -16.014,2.764 -24.615,2.764 -24.812,2.567 -24.812,1.039
GND on Bottom Layer "NONET_L03_P-001" (solid, remove dead copper, pour order 161): -21.981,11.502 -21.981,13.984 -21.785,14.179 -17.108,14.179 -16.986,14.057 -16.986,11.56 -17.104,11.442 -21.921,11.442
GND on Bottom Layer "NONET_L03_P-001" (solid, remove dead copper, pour order 159): -24.815,5.354 -24.55,5.619 -18.573,5.619 -18.378,5.423 -18.378,3.972 -18.596,3.753 -24.623,3.753 -24.806,3.936
GND on Bottom Layer "GND_L06_P050" (solid, remove dead copper, pour order 50): -3.613,-1.315 -6.407,-1.315 -6.407,1.464 -3.613,1.464
GND on Mid-Layer 1 "NONET_L03_P-001" (solid, remove dead copper, pour order 196): -4.395,27.61 -4.931,27.075 -4.931,24.005 -4.931,9.801 -3.622,8.429 5.566,8.405 5.841,8.405 6.904,7.341 6.904,-2.815 2.024,-7.695 -10.019,-7.695 -10.353,-8.029 -10.353,-24.798 -8.522,-26.629 21.237,-26.629 28.351,-19.515 28.351,17.641 18.382,27.61
GND on Mid-Layer 1 "NONET_L03_P-001" (solid, remove dead copper, pour order 190): -14.549,-12.2 -14.549,10.15 -14.217,10.482 -12.757,10.482 -12.537,10.262 -12.537,8.487 -12.077,8.026 5.071,8.026 5.419,7.679 5.419,-3.688 1.974,-7.133 -10.746,-7.133 -11.142,-7.529 -11.142,-11.772 -11.697,-12.327 -14.423,-12.327
10.4V on Mid-Layer 4 "NONET_L03_P-001" (solid, remove dead copper, pour order 198): -6.46,-5.393 2.946,-5.393 5.397,-2.942 5.397,25.125 4.506,26.015 -1.855,26.015 -2.31,25.56 -2.31,15.924 -4.021,14.214 -4.021,7.038 -4.771,6.288 -9.527,6.288 -10.069,5.745 -10.069,-1.722 -7.984,-3.808
P+ on Mid-Layer 4 "NONET_L03_P-001" (solid, remove dead copper, pour order 191): -22.544,25.043 -6.188,25.043 -5.539,24.394 -5.539,8.938 -6.034,8.443 -14.068,8.443 -14.562,7.95 -14.562,-11.764 -15.012,-12.214 -26.123,-12.214 -28.88,-9.457 -28.88,18.706
GND on Mid-Layer 5 "NONET_L03_P-001" (solid, remove dead copper, pour order 199): 8.278,27.634 11.707,24.204 11.707,13.576 6.594,8.463 -2.591,8.463 -4.089,9.961 -4.089,21.118 -4.146,21.174 -5.465,21.174 -5.539,21.095 -5.539,8.938 -6.034,8.443 -14.068,8.443 -14.562,7.95 -14.562,-11.764 -15.012,-12.214 -26.123,-12.214 -28.88,-9.457 -28.88,18.706 -19.953,27.634
3.3V on Mid-Layer 5 "NONET_L03_P-001" (solid, remove dead copper, pour order 195): 6.904,7.341 18.609,19.046 24.604,19.046 28.351,15.228 28.351,-19.515 21.237,-26.629 -8.522,-26.629 -10.378,-24.773 -10.378,-8.054 -10.019,-7.695 2.024,-7.695 6.904,-2.815
GND on Mid-Layer 3 "NONET_L03_P-001" (solid, remove dead copper, pour order 192): -20.824,26.763 -1.351,26.763 -0.676,26.087 -0.676,9.178 -1.41,8.443 -12.089,8.443 -12.874,7.657 -12.874,-11.947 -13.142,-12.214 -26.123,-12.214 -28.88,-9.457 -28.88,18.706

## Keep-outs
Keep-Out Layer:
  circle w0.051: c-2.476,-13.61 r0.305
  circle w0.051: c-2.476,-9.136 r0.305
  circle w0.051: c-15.36,-4.465 r0.305
  circle w0.051: c-15.36,3.339 r0.305
  circle w0.127: c0,0 r26.5

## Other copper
Top Layer:
  pour cut-out: 14.622,10.788 18.628,10.788 18.628,7.481 14.622,7.481
Bottom Layer:
  region net W: -21.283,8.235 -14.84,8.235 -14.739,8.336 -13.592,8.336 -13.56,8.304 -13.56,7.393 -13.631,7.322 -18.112,7.322 -18.229,7.205 -18.229,6.311 -18.434,6.106 -21.295,6.106
  region net U: -21.159,-7.101 -14.469,-7.101 -14.272,-6.904 -13.452,-6.904 -13.452,-7.909 -13.551,-8.009 -17.986,-8.009 -18.107,-8.13 -18.107,-9.058 -18.277,-9.228 -21.172,-9.228
  region net V: -21.238,0.446 -13.496,0.446 -13.496,-0.361 -13.58,-0.446 -18.064,-0.446 -18.186,-0.568 -18.186,-1.459 -18.394,-1.667 -21.25,-1.667

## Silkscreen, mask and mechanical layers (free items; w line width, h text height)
Top Overlay:
  lines w0.127: -9.032,6.249 -9.032,6.588 ; -8.882,-12.411 -8.676,-12.205 -8.434,-12.205 ; -6.291,-12.874 -6.291,-12.464 ; -2.917,-20.079 -2.802,-19.965 -1.465,-19.965 ; 3.937,-9.554 2.86,-9.554 2.86,-8.128 3.947,-8.128 ; 12.363,-14.535 16.055,-14.535 17.167,-15.647 18.055,-15.647 18.658,-15.043 19.297,-15.043 ; 12.37,-15.969 12.823,-15.517 16.162,-15.517 16.801,-16.156 18.173,-16.156 ; 23.329,7.947 21.795,7.947 21.795,9.403 23.346,9.403 ; 3.947,-8.128 3.947,-13.448 7.954,-13.448 7.954,-8.128 3.947,-8.128 ; 23.346,9.403 24.352,9.403 24.718,9.037 24.718,7.955 24.923,7.75 24.923,6.367 24.923,6.262 25.727,5.458 25.727,3.609 26.121,3.215 26.121,0.669 23.714,0.669 23.346,1.037 23.346,9.403 ; -12.365,20.689 -12.365,23.214 -6.926,24.937 -6.926,21.531 -8.377,21.531 -8.377,17.3 -11.447,17.3 -11.447,19.771 -12.365,20.689 ; -6.601,21.212 -6.601,25.357 -5.102,25.357 -4.567,25.892 -2.911,25.892 -2.911,21.212 -6.601,21.212
  text "4" at -5.317,24.58 h0.89 r90
  text "P+" at -7.593,22.368 h0.89 r90
  text "GND" at -5.397,22.197 h0.89 r90
  text "3" at -5.317,21.368 h0.89 r90
  text "2" at -10.962,21.275 h0.89 r90
  text "1" at -10.121,19.808 h0.89 r90
  text "YCD4_CYRL_V2.00_2" at -5.209,8.534 h0.89
  text "A" at 22.246,8.289 h0.89
  text "20" at 24.516,7.703 h0.89 r90
  text "W" at -22.175,6.655 h0.89
  text "19" at 24.211,3.87 h0.71 r90
  text "18" at 24.243,2.768 h0.71 r90
  text "17" at 24.506,0.96 h0.89 r90
  text "V" at -22.248,-1.014 h0.89
  text "3.3V" at 24.689,-1.808 h0.71 r90
  text "16" at 26.338,-2.051 h0.71 r90
  text "15" at 24.618,-4.147 h0.89
  text "GND" at 24.075,-5.08 h0.71
  text "U" at -22.224,-8.609 h0.89
  text "RS485_B" at 18.383,-8.887 h0.71
  text "Net1_6" at 4.416,-9.208 h0.71
  text "A" at 3.021,-9.285 h0.89
  text "RS485_A" at 18.347,-10.149 h0.71
  text "Net1_5" at 4.429,-10.409 h0.71
  text "14" at 23.929,-10.969 h0.76 r70
  text "SWCLK" at 4.416,-11.895 h0.71
  text "13" at 22.832,-13.049 h0.76 r60
  text "SWDIO" at 4.456,-13.147 h0.71
  text "GND" at 20.097,-13.291 h0.71 r45
  text "RS232_RX" at 5.959,-14.967 h0.89
  text "12" at 21.223,-15.08 h0.89 r45
  text "5" at -4.595,-15.709 h0.89 r90
  text "GND" at 15.361,-16.189 h0.71 r315
  text "RS232_TX" at 5.964,-16.427 h0.89
  text "11" at 20.096,-16.838 h0.89 r45
  text "SPI_CLK+" at -11.583,-16.949 h0.89
  text "10" at 18.816,-18.35 h0.89 r45
  text "SPI_CLK-" at -11.524,-18.893 h0.89
  text "9" at 17.656,-19.356 h0.89 r45
  text "6" at -4.594,-19.721 h0.89 r90
  text "SPI_DA+" at -11.762,-20.793 h0.89
  text "7" at -8.447,-22.105 h0.89 r90
  text "SPI_DA-" at -13.479,-22.517 h0.89 r345
  text "8" at -7.11,-24.956 h0.89 r90
Bottom Overlay:
  lines w0.127: -0.33,-11.356 -0.022,-11.356
  text "YCD4_CYRL_V2.00_2" at 8.734,8.449 h0.89
Bottom Solder:
  drawing of 17 lines, arcs and shapes, not listed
